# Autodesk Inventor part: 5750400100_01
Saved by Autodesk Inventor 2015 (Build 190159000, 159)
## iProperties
Created: 2020-07
Part Number: 5750400100_01
Checked By: TraceParts S.A.
Material: Generic
Catalog Web Link: www.traceparts.com
Document SubType Name: Modeling
Designer: TraceParts
Density: 1 g/cm^3
Appearance: Default
Company: TraceParts S.A.
Author: TraceParts
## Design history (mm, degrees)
feature "5750400100_01.ipt"
body "Solid1"
